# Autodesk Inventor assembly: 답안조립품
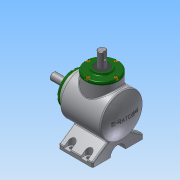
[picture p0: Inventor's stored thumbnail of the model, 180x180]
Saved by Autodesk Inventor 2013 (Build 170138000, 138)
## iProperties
Created: 2017-04
Part Number: 답안조립품
Document SubType Name: Assembly
Designer: Administrator
Author: Administrator
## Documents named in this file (14)
- C:\Users\Administrator\Desktop\470407V1007\답안조립품.iam
- C:\Users\Administrator\Desktop\470407V1007\본체.ipt
- C:\Users\Administrator\Desktop\470407V1007\커버.ipt
- C:\Users\Administrator\Desktop\470407V1007\메인 축.ipt
- 메인 축.ipt
- C:\Users\Administrator\Desktop\470407V1007\메인 베벨기어.ipt
- C:\Users\Administrator\Desktop\470407V1007\키 5x5.ipt
- C:\Users\Administrator\Desktop\470407V1007\베어링 6203.ipt
- C:\Users\Administrator\Desktop\470407V1007\서브 축.ipt
- 서브 축.ipt
- C:\Users\Administrator\Desktop\470407V1007\서브 베벨기어.ipt
- C:\Users\Administrator\Desktop\470407V1007\오일실 17 32 8.ipt
- C:\Users\Administrator\Desktop\470407V1007\키 4x4.ipt
- C:\Users\Administrator\Desktop\470407V1007\볼트 M4.ipt
